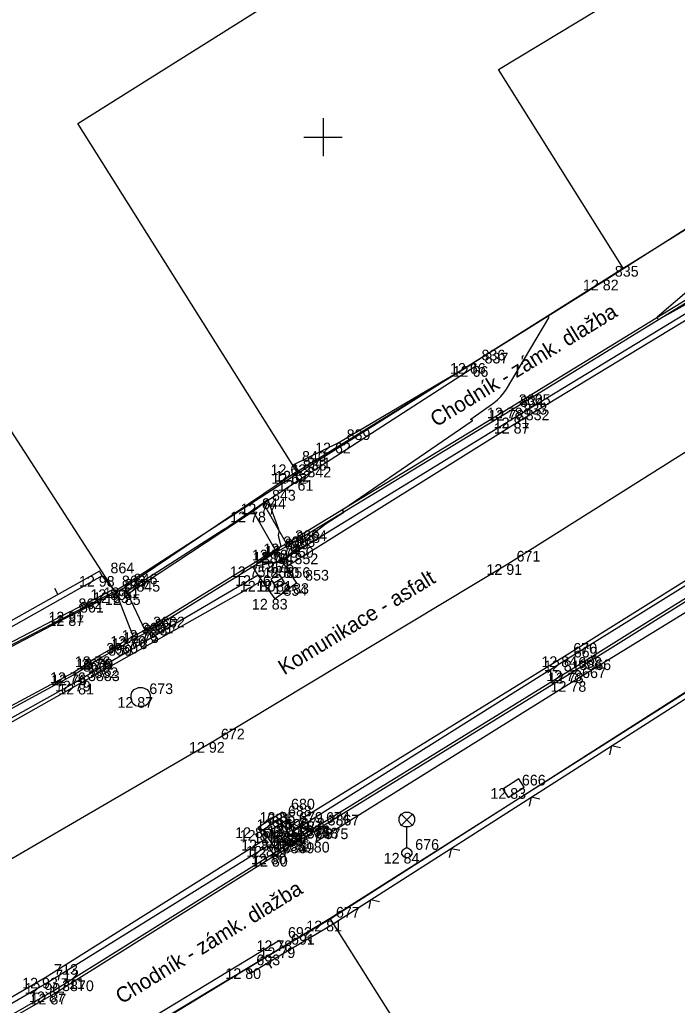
# Model space of a CAD drawing. Extents: x -703403 to -701924, y -1022520 to -1021856.
# Drawn here: x -703282.96 to -703265.7, y -1022172.79 to -1022146.91 of the extents above; entities that cross this region are included whole.
import ezdxf

# ---------------------------------------------------------------- set-up
doc = ezdxf.new("R2010")
doc.units = 0
for name, color, linetype in [('Ex_Minor Contours', 7, 'Continuous'), ('Z_body', 7, 'Continuous'), ('Z_body_cisla', 7, 'Continuous'), ('Z_body_vysky_redukovane', 7, 'Continuous'), ('Z_budova', 7, 'Continuous'), ('Z_chodnik', 7, 'Continuous'), ('Z_hektometricka_sit', 7, 'Continuous'), ('Z_katastr_hranice', 7, 'Continuous'), ('Z_katastr_vnitrni_kresba', 7, 'Continuous'), ('Z_komunikace', 7, 'Continuous'), ('Z_komunikace_osa', 7, 'Continuous'), ('Z_obruba', 7, 'Continuous'), ('Z_pilire', 7, 'Continuous'), ('Z_ploty', 7, 'Continuous'), ('Z_ploty_znacky', 7, 'Continuous'), ('Z_popisy', 7, 'Continuous'), ('Z_rozhranni', 7, 'Continuous'), ('Z_site_kanalizace_znaky', 7, 'Continuous'), ('Z_site_vo_znaky', 7, 'Continuous'), ('Z_vstupy', 7, 'Continuous'), ('Z_zlabek', 7, 'Continuous')]:
    doc.layers.add(name, color=color, linetype=linetype)

# ---------------------------------------------------------------- blocks, each defined once
blk = doc.blocks.new('POINT_DISPLAY')
blk.add_line((0, 0), (0, 0))
blk = doc.blocks.new('Z34')
for p, q in [((-0.15, 1.02), (-0.05, 1.07)), ((-0.05, 1.07), (0.05, 1.07)), ((0.05, 1.07), (0.15, 1.02)), ((-0.2, 0.93), (-0.15, 1.02)), ((-0.2, 0.82), (-0.2, 0.93)), ((-0.15, 0.72), (-0.2, 0.82)), ((0.15, 0.72), (-0.15, 1.02)), ((0.15, 1.02), (-0.15, 0.72)), ((0.15, 1.02), (0.2, 0.93)), ((0.2, 0.82), (0.15, 0.72)), ((0.2, 0.93), (0.2, 0.82)), ((-0.05, 0.68), (-0.15, 0.72)), ((0.05, 0.68), (-0.05, 0.68)), ((0, 0.13), (0, 0.68)), ((0.15, 0.72), (0.05, 0.68)), ((-0.13, 0.03), (-0.1, 0.08)), ((-0.13, -0.03), (-0.13, 0.03)), ((-0.1, 0.08), (-0.08, 0.1)), ((-0.08, 0.1), (-0.03, 0.13)), ((-0.03, 0.13), (0.03, 0.13)), ((0.03, 0.13), (0.08, 0.1)), ((0.08, 0.1), (0.1, 0.08)), ((0.1, 0.08), (0.13, 0.03)), ((0.13, 0.03), (0.13, -0.03)), ((-0.1, -0.08), (-0.13, -0.03)), ((-0.08, -0.1), (-0.1, -0.08)), ((-0.03, -0.13), (-0.08, -0.1)), ((0.03, -0.13), (-0.03, -0.13)), ((0.08, -0.1), (0.03, -0.13)), ((0.1, -0.08), (0.08, -0.1)), ((0.13, -0.03), (0.1, -0.08))]:
    blk.add_line(p, q)
blk = doc.blocks.new('Z666')
for p, q in [((-0.25, 0.13), (-0.25, -0.13)), ((0.25, 0.13), (-0.25, 0.13)), ((0.25, -0.13), (0.25, 0.13)), ((-0.25, -0.13), (0.25, -0.13))]:
    blk.add_line(p, q)
blk = doc.blocks.new('Z620')
for p, q in [((-0.25, 0.05), (-0.23, 0.13)), ((-0.25, -0.05), (-0.25, 0.05)), ((-0.23, 0.13), (-0.17, 0.2)), ((-0.17, 0.2), (-0.05, 0.25)), ((-0.05, 0.25), (0.05, 0.25)), ((0.05, 0.25), (0.17, 0.2)), ((0.17, 0.2), (0.23, 0.13)), ((0.23, 0.13), (0.25, 0.05)), ((0.25, 0.05), (0.25, -0.05)), ((-0.2, -0.17), (-0.25, -0.05)), ((-0.13, -0.23), (-0.2, -0.17)), ((-0.05, -0.25), (-0.13, -0.23)), ((0.05, -0.25), (-0.05, -0.25)), ((0.13, -0.23), (0.05, -0.25)), ((0.2, -0.17), (0.13, -0.23)), ((0.25, -0.05), (0.2, -0.17))]:
    blk.add_line(p, q)
blk = doc.blocks.new('Z46260')
for p, q in [((0.13, 0.13), (-0.13, 0.13)), ((-0.13, 0.13), (-0.13, -0.13)), ((0.13, 0), (-0.13, 0)), ((0.13, -0.13), (0.13, 0.13)), ((-0.13, -0.13), (0.13, -0.13))]:
    blk.add_line(p, q)
blk = doc.blocks.new('Z210')
blk.add_line((0, 0), (0, 0.17))
blk = doc.blocks.new('Z212')
for p, q in [((-0.17, 0.17), (0, 0)), ((0, 0), (0.17, 0.17))]:
    blk.add_line(p, q)

msp = doc.modelspace()

# ---------------------------------------------------------------- linework, layer by layer
at = {"layer": 'Ex_Minor Contours'}
for points in [[(-703264.422, -1022153.187), (-703266.229, -1022154.725), (-703266.231, -1022154.727), (-703266.232, -1022154.731), (-703266.232, -1022154.734), (-703266.231, -1022154.738), (-703266.224, -1022154.753), (-703266.22, -1022154.76), (-703266.215, -1022154.767), (-703266.205, -1022154.783), (-703266.202, -1022154.786), (-703266.199, -1022154.787), (-703266.196, -1022154.787), (-703266.192, -1022154.786), (-703262.3, -1022152.622)], [(-703280.346, -1022161.903), (-703280.202, -1022161.919), (-703280.178, -1022161.92), (-703280.155, -1022161.917), (-703280.133, -1022161.91), (-703280.112, -1022161.899), (-703277.628, -1022160.311), (-703277.526, -1022160.246), (-703277.426, -1022160.18), (-703277.325, -1022160.113), (-703277.225, -1022160.046), (-703276.672, -1022159.671), (-703276.65, -1022159.656), (-703276.628, -1022159.64), (-703276.606, -1022159.625), (-703276.584, -1022159.609), (-703276.458, -1022159.518), (-703276.455, -1022159.516), (-703276.453, -1022159.516), (-703276.451, -1022159.518), (-703276.45, -1022159.521), (-703276.445, -1022159.539), (-703276.441, -1022159.55), (-703276.172, -1022160.287), (-703276.167, -1022160.304), (-703276.164, -1022160.32), (-703276.163, -1022160.338), (-703276.164, -1022160.355), (-703276.173, -1022160.425), (-703276.175, -1022160.442), (-703276.174, -1022160.46), (-703276.173, -1022160.477), (-703276.17, -1022160.494), (-703276.12, -1022160.708), (-703276.118, -1022160.728), (-703276.121, -1022160.746), (-703276.13, -1022160.763), (-703276.144, -1022160.778), (-703276.211, -1022160.833), (-703276.228, -1022160.846), (-703276.246, -1022160.859), (-703276.263, -1022160.872), (-703276.281, -1022160.885), (-703276.691, -1022161.168), (-703276.745, -1022161.21), (-703276.759, -1022161.236), (-703276.731, -1022161.244), (-703276.663, -1022161.235), (-703276.278, -1022161.158), (-703276.186, -1022161.133), (-703276.101, -1022161.098), (-703276.02, -1022161.053), (-703275.945, -1022160.996), (-703275.209, -1022160.369), (-703275.138, -1022160.31), (-703275.065, -1022160.253), (-703274.991, -1022160.198), (-703274.915, -1022160.146), (-703274.456, -1022159.84), (-703274.455, -1022159.839), (-703274.454, -1022159.837), (-703274.454, -1022159.836), (-703274.455, -1022159.834), (-703274.485, -1022159.789), (-703274.488, -1022159.783), (-703274.488, -1022159.778), (-703274.486, -1022159.774), (-703274.481, -1022159.77), (-703271.082, -1022157.445), (-703271.077, -1022157.44), (-703271.075, -1022157.436), (-703271.078, -1022157.433), (-703271.084, -1022157.429), (-703271.116, -1022157.417), (-703271.123, -1022157.414), (-703271.125, -1022157.41), (-703271.124, -1022157.406), (-703271.118, -1022157.401), (-703270.519, -1022156.973), (-703270.422, -1022156.896), (-703270.334, -1022156.81), (-703270.255, -1022156.715), (-703270.186, -1022156.612), (-703269.072, -1022154.743), (-703269.07, -1022154.738), (-703269.07, -1022154.733), (-703269.071, -1022154.729), (-703269.074, -1022154.724), (-703269.097, -1022154.698)], [(-703279.64, -1022163), (-703276.84, -1022161.27)]]:
    msp.add_lwpolyline(points, dxfattribs=at)
at = {"layer": 'Z_budova'}
for p, q in [((-703259.29, -1022148.47), (-703267.57, -1022153.74)), ((-703267.57, -1022153.74), (-703271.06, -1022155.93)), ((-703275.77, -1022158.59), (-703275.65, -1022158.76)), ((-703275.75, -1022158.82), (-703280.2, -1022161.82)), ((-703275.65, -1022158.76), (-703275.75, -1022158.82)), ((-703280.8, -1022161.52), (-703280.87, -1022161.39)), ((-703280.5, -1022161.87), (-703280.8, -1022161.52)), ((-703280.43, -1022161.95), (-703280.5, -1022161.87)), ((-703280.2, -1022161.82), (-703280.43, -1022161.95))]:
    msp.add_line(p, q, dxfattribs=at)
at = {"layer": 'Z_chodnik'}
for p, q in [((-703275.63, -1022159), (-703276.56, -1022159.62)), ((-703276.56, -1022159.62), (-703276.83, -1022159.83)), ((-703276.83, -1022159.83), (-703280.12, -1022162)), ((-703281.6, -1022162.55), (-703280.43, -1022161.95)), ((-703281.6, -1022162.55), (-703288.9, -1022166.36))]:
    msp.add_line(p, q, dxfattribs=at)
at = {"layer": 'Z_hektometricka_sit'}
for p, q in [((-703275, -1022149.5), (-703275, -1022150.5)), ((-703275.5, -1022150), (-703274.5, -1022150))]:
    msp.add_line(p, q, dxfattribs=at)
at = {"layer": 'Z_katastr_hranice'}
for p, q in [((-703267.12, -1022153.44), (-703258.63, -1022148.12)), ((-703289.16, -1022148.5), (-703280.47, -1022161.93)), ((-703275.66, -1022158.82), (-703267.12, -1022153.44)), ((-703280.47, -1022161.93), (-703275.66, -1022158.82)), ((-703286.64, -1022165.11), (-703280.47, -1022161.93)), ((-703263.07, -1022163.05), (-703274.81, -1022170.51)), ((-703274.81, -1022170.51), (-703280.91, -1022174.18)), ((-703266.89, -1022183.1), (-703274.81, -1022170.51))]:
    msp.add_line(p, q, dxfattribs=at)
at = {"layer": 'Z_katastr_vnitrni_kresba'}
for p, q in [((-703270.39, -1022148.22), (-703261.74, -1022142.98)), ((-703281.44, -1022149.64), (-703275, -1022145.59)), ((-703267.12, -1022153.44), (-703270.39, -1022148.22)), ((-703275.66, -1022158.82), (-703281.44, -1022149.64))]:
    msp.add_line(p, q, dxfattribs=at)
at = {"layer": 'Z_komunikace'}
for p, q in [((-703262.14, -1022152.78), (-703269.91, -1022157.5)), ((-703269.91, -1022157.5), (-703275.98, -1022161.29)), ((-703259.69, -1022158.01), (-703268.66, -1022163.63)), ((-703275.98, -1022161.29), (-703275.7, -1022161.71)), ((-703276.6, -1022161.65), (-703281.39, -1022164.35)), ((-703276.26, -1022162.12), (-703276.6, -1022161.65)), ((-703275.7, -1022161.71), (-703276.26, -1022162.12)), ((-703268.66, -1022163.63), (-703275.85, -1022168.08)), ((-703281.39, -1022164.35), (-703287.19, -1022167.62)), ((-703276.06, -1022167.72), (-703276.7, -1022168.12)), ((-703275.85, -1022168.08), (-703276.06, -1022167.72)), ((-703276.7, -1022168.12), (-703276.54, -1022168.45)), ((-703276.54, -1022168.45), (-703282.29, -1022172.07)), ((-703282.29, -1022172.07), (-703287.29, -1022174.96))]:
    msp.add_line(p, q, dxfattribs=at)
at = {"layer": 'Z_komunikace_osa'}
for p, q in [((-703261.03, -1022155.45), (-703270.15, -1022161.21)), ((-703270.15, -1022161.21), (-703277.91, -1022165.88)), ((-703277.91, -1022165.88), (-703283.89, -1022169.36))]:
    msp.add_line(p, q, dxfattribs=at)
at = {"layer": 'Z_obruba'}
for p, q in [((-703270.09, -1022157.1), (-703262.38, -1022152.36)), ((-703262.23, -1022152.66), (-703269.96, -1022157.36)), ((-703275.96, -1022160.67), (-703270.09, -1022157.1)), ((-703269.96, -1022157.36), (-703276.09, -1022161.12)), ((-703259.63, -1022158.12), (-703268.64, -1022163.74)), ((-703276.26, -1022160.83), (-703275.96, -1022160.67)), ((-703279.68, -1022162.94), (-703276.26, -1022160.83)), ((-703276.7, -1022161.5), (-703281.43, -1022164.27)), ((-703268.49, -1022164.06), (-703264.42, -1022161.52)), ((-703281.65, -1022162.46), (-703280.5, -1022161.87)), ((-703281.65, -1022162.46), (-703288.95, -1022166.27)), ((-703280.91, -1022163.63), (-703279.98, -1022163.1)), ((-703279.98, -1022163.1), (-703279.68, -1022162.94)), ((-703281.56, -1022164.05), (-703280.91, -1022163.63)), ((-703268.64, -1022163.74), (-703275.8, -1022168.24)), ((-703287.4, -1022167.19), (-703281.56, -1022164.05)), ((-703275.1, -1022168.14), (-703268.49, -1022164.06)), ((-703281.43, -1022164.27), (-703287.21, -1022167.5)), ((-703275.65, -1022168.48), (-703275.1, -1022168.14)), ((-703276.28, -1022168.87), (-703275.65, -1022168.48)), ((-703276.46, -1022168.61), (-703282.25, -1022172.21)), ((-703282.07, -1022172.49), (-703276.28, -1022168.87)), ((-703282.25, -1022172.21), (-703287.23, -1022175.09)), ((-703287.02, -1022175.32), (-703282.07, -1022172.49))]:
    msp.add_line(p, q, dxfattribs=at)
at = {"layer": 'Z_ploty'}
for p, q in [((-703280.87, -1022161.39), (-703284.76, -1022163.58)), ((-703280.8, -1022161.52), (-703284.69, -1022163.71)), ((-703274.88, -1022170.57), (-703263.42, -1022163.24)), ((-703274.8, -1022170.7), (-703263.35, -1022163.37)), ((-703276.06, -1022171.27), (-703274.88, -1022170.57)), ((-703275.98, -1022171.39), (-703274.8, -1022170.7)), ((-703276.98, -1022171.82), (-703276.06, -1022171.27)), ((-703276.9, -1022171.95), (-703275.98, -1022171.39)), ((-703276.98, -1022171.82), (-703276.9, -1022171.95))]:
    msp.add_line(p, q, dxfattribs=at)
at = {"layer": 'Z_rozhranni'}
for p, q in [((-703276.23, -1022160.89), (-703276.09, -1022161.12)), ((-703276.7, -1022161.5), (-703276.84, -1022161.27)), ((-703276.09, -1022161.12), (-703275.98, -1022161.29)), ((-703276.6, -1022161.65), (-703276.7, -1022161.5)), ((-703276.14, -1022167.91), (-703276.58, -1022168.19)), ((-703275.86, -1022168.32), (-703276.14, -1022167.91)), ((-703276.58, -1022168.19), (-703276.29, -1022168.63)), ((-703275.85, -1022168.08), (-703275.8, -1022168.24)), ((-703275.8, -1022168.24), (-703275.68, -1022168.42)), ((-703276.54, -1022168.45), (-703276.46, -1022168.61)), ((-703276.29, -1022168.63), (-703275.86, -1022168.32)), ((-703276.46, -1022168.61), (-703276.31, -1022168.81))]:
    msp.add_line(p, q, dxfattribs=at)
at = {"layer": 'Z_vstupy'}
for p, q in [((-703274.6, -1022158.02), (-703271.06, -1022155.93)), ((-703275.77, -1022158.59), (-703274.6, -1022158.02)), ((-703280.02, -1022173.66), (-703276.98, -1022171.82))]:
    msp.add_line(p, q, dxfattribs=at)
at = {"layer": 'Z_zlabek'}
for p, q in [((-703270.05, -1022157.16), (-703262.35, -1022152.42)), ((-703275.65, -1022158.76), (-703271.06, -1022155.93)), ((-703270.99, -1022156.01), (-703275.63, -1022159)), ((-703271.06, -1022155.93), (-703270.99, -1022156.01)), ((-703275.92, -1022160.73), (-703270.05, -1022157.16)), ((-703275.63, -1022159), (-703275.75, -1022158.82)), ((-703275.96, -1022160.67), (-703276.56, -1022159.62)), ((-703276.83, -1022159.83), (-703276.26, -1022160.83)), ((-703276.23, -1022160.89), (-703275.92, -1022160.73)), ((-703276.84, -1022161.27), (-703276.23, -1022160.89)), ((-703279.64, -1022163), (-703276.84, -1022161.27)), ((-703268.53, -1022164), (-703264.46, -1022161.46)), ((-703264.4, -1022161.81), (-703268.42, -1022164.28)), ((-703279.98, -1022163.1), (-703280.43, -1022161.95)), ((-703280.2, -1022161.82), (-703280.12, -1022162)), ((-703280.12, -1022162), (-703279.68, -1022162.94)), ((-703279.94, -1022163.16), (-703279.64, -1022163)), ((-703280.87, -1022163.69), (-703279.94, -1022163.16)), ((-703281.53, -1022164.11), (-703280.87, -1022163.69)), ((-703287.37, -1022167.26), (-703281.53, -1022164.11)), ((-703275.14, -1022168.08), (-703268.53, -1022164)), ((-703268.42, -1022164.28), (-703275.18, -1022168.5)), ((-703275.68, -1022168.42), (-703275.14, -1022168.08)), ((-703275.18, -1022168.5), (-703275.1, -1022168.14)), ((-703276.31, -1022168.81), (-703275.68, -1022168.42)), ((-703282.11, -1022172.43), (-703276.31, -1022168.81)), ((-703276.14, -1022171.09), (-703280.22, -1022173.56)), ((-703276.14, -1022171.09), (-703276.06, -1022171.27)), ((-703287.06, -1022175.26), (-703282.11, -1022172.43))]:
    msp.add_line(p, q, dxfattribs=at)

# ---------------------------------------------------------------- block references
at = {"layer": 'Z_body'}
for p in [(-703267.57, -1022153.74), (-703271.06, -1022155.93), (-703270.99, -1022156.01), (-703270.09, -1022157.1), (-703270.05, -1022157.16), (-703269.96, -1022157.36), (-703269.91, -1022157.5), (-703274.6, -1022158.02), (-703275.77, -1022158.59), (-703275.75, -1022158.82), (-703275.65, -1022158.76), (-703275.63, -1022159), (-703276.56, -1022159.62), (-703276.83, -1022159.83), (-703275.96, -1022160.67), (-703275.92, -1022160.73), (-703276.26, -1022160.83), (-703276.23, -1022160.89), (-703276.84, -1022161.27), (-703276.09, -1022161.12), (-703275.98, -1022161.29), (-703270.15, -1022161.21), (-703280.8, -1022161.52), (-703276.7, -1022161.5), (-703276.6, -1022161.65), (-703276.19, -1022161.65), (-703275.7, -1022161.71), (-703280.5, -1022161.87), (-703280.43, -1022161.95), (-703280.2, -1022161.82), (-703280.12, -1022162), (-703276.26, -1022162.12), (-703281.65, -1022162.46), (-703281.6, -1022162.55), (-703279.98, -1022163.1), (-703279.68, -1022162.94), (-703279.64, -1022163), (-703279.94, -1022163.16), (-703280.91, -1022163.63), (-703280.87, -1022163.69), (-703268.66, -1022163.63), (-703268.64, -1022163.74), (-703281.56, -1022164.05), (-703281.53, -1022164.11), (-703268.53, -1022164), (-703268.49, -1022164.06), (-703281.43, -1022164.27), (-703281.39, -1022164.35), (-703268.42, -1022164.28), (-703279.79, -1022164.7), (-703277.91, -1022165.88), (-703270, -1022167.09), (-703276.06, -1022167.72), (-703276.14, -1022167.91), (-703276.7, -1022168.12), (-703276.58, -1022168.19), (-703276.22, -1022168.25), (-703275.85, -1022168.08), (-703275.8, -1022168.24), (-703275.14, -1022168.08), (-703275.1, -1022168.14), (-703276.54, -1022168.45), (-703275.86, -1022168.32), (-703275.68, -1022168.42), (-703275.65, -1022168.48), (-703275.18, -1022168.5), (-703276.46, -1022168.61), (-703276.29, -1022168.63), (-703272.8, -1022168.79), (-703276.31, -1022168.81), (-703276.28, -1022168.87), (-703274.88, -1022170.57), (-703276.14, -1022171.09), (-703276.06, -1022171.27), (-703276.98, -1022171.82), (-703282.29, -1022172.07), (-703282.25, -1022172.21), (-703282.11, -1022172.43), (-703282.07, -1022172.49)]:
    msp.add_blockref('POINT_DISPLAY', p, dxfattribs=at)
at = {"layer": 'Z_pilire', "rotation": 32.4}
msp.add_blockref('Z666', (-703270, -1022167.09), dxfattribs=at)
at = {"layer": 'Z_ploty_znacky'}
for name, p, rotation in [('Z210', (-703281.96, -1022162), 29.4), ('Z212', (-703267.43, -1022165.98), -147.4), ('Z212', (-703269.54, -1022167.33), -147.4), ('Z212', (-703271.64, -1022168.68), -147.4), ('Z212', (-703273.75, -1022170.02), -147.4), ('Z210', (-703275.39, -1022171.05), -149.40000000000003), ('Z210', (-703276.44, -1022171.67), -148.90000000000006)]:
    msp.add_blockref(name, p, dxfattribs=dict(at, rotation=rotation))
at = {"layer": 'Z_site_kanalizace_znaky', "rotation": 31.5}
for p in [(-703276.19, -1022161.65), (-703276.22, -1022168.25)]:
    msp.add_blockref('Z46260', p, dxfattribs=at)
at = {"layer": 'Z_site_kanalizace_znaky'}
msp.add_blockref('Z620', (-703279.79, -1022164.7), dxfattribs=at)
at = {"layer": 'Z_site_vo_znaky'}
msp.add_blockref('Z34', (-703272.8, -1022168.79), dxfattribs=at)

# ---------------------------------------------------------------- texts
at = {"layer": 'Z_body_cisla'}
for s, p in [('835', (-703267.34, -1022153.66)), ('836', (-703270.84, -1022155.86)), ('837', (-703270.76, -1022155.94)), ('3665', (-703269.86, -1022157.03)), ('834', (-703269.83, -1022157.08)), ('833', (-703269.74, -1022157.28)), ('832', (-703269.68, -1022157.43)), ('839', (-703274.38, -1022157.95)), ('840', (-703275.55, -1022158.52)), ('841', (-703275.42, -1022158.69)), ('838', (-703275.53, -1022158.75)), ('842', (-703275.41, -1022158.93)), ('844', (-703276.6, -1022159.76)), ('843', (-703276.34, -1022159.54)), ('3663', (-703276.04, -1022160.76)), ('3664', (-703275.73, -1022160.6)), ('848', (-703275.7, -1022160.65)), ('849', (-703276, -1022160.82)), ('850', (-703275.87, -1022161.04)), ('3884', (-703276.61, -1022161.2)), ('852', (-703275.75, -1022161.21)), ('671', (-703269.92, -1022161.14)), ('864', (-703280.58, -1022161.45)), ('851', (-703276.47, -1022161.43)), ('855', (-703276.38, -1022161.57)), ('856', (-703275.96, -1022161.57)), ('863', (-703280.28, -1022161.79)), ('846', (-703279.97, -1022161.74)), ('853', (-703275.47, -1022161.64)), ('847', (-703280.21, -1022161.88)), ('845', (-703279.9, -1022161.93)), ('854', (-703276.04, -1022162.04)), ('862', (-703281.42, -1022162.39)), ('861', (-703281.38, -1022162.48)), ('3662', (-703279.46, -1022162.87)), ('3661', (-703279.76, -1022163.03)), ('858', (-703279.71, -1022163.08)), ('857', (-703279.42, -1022162.93)), ('3660', (-703280.69, -1022163.56)), ('859', (-703280.64, -1022163.61)), ('670', (-703268.43, -1022163.56)), ('669', (-703268.42, -1022163.66)), ('3659', (-703281.34, -1022163.98)), ('860', (-703281.3, -1022164.03)), ('668', (-703268.3, -1022163.93)), ('3866', (-703268.27, -1022163.99)), ('3882', (-703281.21, -1022164.2)), ('3883', (-703281.17, -1022164.28)), ('667', (-703268.2, -1022164.2)), ('673', (-703279.56, -1022164.62)), ('672', (-703277.68, -1022165.81)), ('666', (-703269.78, -1022167.02)), ('680', (-703275.84, -1022167.65)), ('681', (-703276.47, -1022168.04)), ('688', (-703275.92, -1022167.83)), ('679', (-703275.63, -1022168)), ('674', (-703274.92, -1022168)), ('689', (-703276.35, -1022168.11)), ('690', (-703276, -1022168.18)), ('687', (-703275.63, -1022168.24)), ('678', (-703275.58, -1022168.16)), ('3867', (-703274.88, -1022168.07)), ('682', (-703276.31, -1022168.37)), ('683', (-703276.24, -1022168.53)), ('686', (-703276.06, -1022168.56)), ('684', (-703275.46, -1022168.35)), ('3868', (-703275.43, -1022168.41)), ('675', (-703274.96, -1022168.43)), ('685', (-703276.09, -1022168.74)), ('3869', (-703276.06, -1022168.8)), ('676', (-703272.58, -1022168.71)), ('677', (-703274.66, -1022170.49)), ('692', (-703275.92, -1022171.02)), ('691', (-703275.84, -1022171.2)), ('693', (-703276.75, -1022171.74)), ('713', (-703282.06, -1022171.99)), ('712', (-703282.03, -1022172.14)), ('711', (-703281.88, -1022172.36)), ('3870', (-703281.85, -1022172.42))]:
    msp.add_text(s, height=0.28, dxfattribs=at).set_placement(p)
at = {"layer": 'Z_body_vysky_redukovane'}
for s, p in [('12 82', (-703268.177, -1022154.02)), ('12 66', (-703271.667, -1022156.21)), ('12 66', (-703271.597, -1022156.29)), ('12 78', (-703270.697, -1022157.38)), ('12 78', (-703270.657, -1022157.44)), ('12 81', (-703270.52, -1022157.64)), ('12 87', (-703270.517, -1022157.78)), ('12 62', (-703275.207, -1022158.3)), ('12 62', (-703276.377, -1022158.87)), ('12 62', (-703276.357, -1022159.1)), ('12 62', (-703276.257, -1022159.04)), ('12 61', (-703276.19, -1022159.28)), ('12 77', (-703277.167, -1022159.9)), ('12 78', (-703277.437, -1022160.11)), ('12 74', (-703276.567, -1022160.95)), ('12 74', (-703276.527, -1022161.01)), ('12 76', (-703276.867, -1022161.11)), ('12 74', (-703276.837, -1022161.17)), ('12 75', (-703277.447, -1022161.55)), ('12 75', (-703276.697, -1022161.4)), ('12 80', (-703276.563, -1022161.57)), ('12 91', (-703270.71, -1022161.49)), ('12 98', (-703281.407, -1022161.8)), ('12 76', (-703277.307, -1022161.78)), ('12 80', (-703277.183, -1022161.93)), ('12 81', (-703276.75, -1022161.93)), ('12 83', (-703276.307, -1022161.99)), ('12 89', (-703281.107, -1022162.15)), ('12 83', (-703281.037, -1022162.23)), ('12 61', (-703280.76, -1022162.1)), ('12 85', (-703280.727, -1022162.28)), ('12 83', (-703276.867, -1022162.4)), ('12 91', (-703282.21, -1022162.74)), ('12 87', (-703282.207, -1022162.83)), ('12 76', (-703280.587, -1022163.38)), ('12 76', (-703280.287, -1022163.22)), ('12 75', (-703280.247, -1022163.28)), ('12 76', (-703280.547, -1022163.44)), ('12 76', (-703281.517, -1022163.91)), ('12 84', (-703269.267, -1022163.91)), ('12 76', (-703281.477, -1022163.97)), ('12 81', (-703269.2, -1022164.02)), ('12 76', (-703282.167, -1022164.33)), ('12 76', (-703282.137, -1022164.39)), ('12 78', (-703269.137, -1022164.28)), ('12 78', (-703269.097, -1022164.34)), ('12 79', (-703282.037, -1022164.55)), ('12 81', (-703281.95, -1022164.63)), ('12 78', (-703269.027, -1022164.56)), ('12 87', (-703280.397, -1022164.98)), ('12 92', (-703278.517, -1022166.16)), ('12 83', (-703270.607, -1022167.37)), ('12 85', (-703276.667, -1022168)), ('12 84', (-703276.747, -1022168.19)), ('12 86', (-703277.307, -1022168.4)), ('12 84', (-703277.187, -1022168.47)), ('12 82', (-703276.827, -1022168.53)), ('12 83', (-703276.457, -1022168.36)), ('12 80', (-703276.383, -1022168.52)), ('12 78', (-703275.747, -1022168.36)), ('12 80', (-703275.683, -1022168.42)), ('12 84', (-703277.147, -1022168.73)), ('12 79', (-703276.467, -1022168.6)), ('12 79', (-703276.287, -1022168.7)), ('12 80', (-703276.233, -1022168.76)), ('12 80', (-703275.763, -1022168.78)), ('12 81', (-703277.02, -1022168.89)), ('12 79', (-703276.897, -1022168.91)), ('12 84', (-703273.407, -1022169.07)), ('12 80', (-703276.893, -1022169.09)), ('12 80', (-703276.863, -1022169.15)), ('12 81', (-703275.44, -1022170.85)), ('12 78', (-703276.747, -1022171.37)), ('12 79', (-703276.667, -1022171.55)), ('12 80', (-703277.563, -1022172.1)), ('12 93', (-703282.897, -1022172.35)), ('12 90', (-703282.833, -1022172.49)), ('12 87', (-703282.717, -1022172.71)), ('12 87', (-703282.677, -1022172.77))]:
    msp.add_text(s, height=0.28, dxfattribs=at).set_placement(p)
at = {"layer": 'Z_popisy'}
for s, p in [('Chodník - zámk. dlažba', (-703272.03, -1022157.62)), ('Komunikace - asfalt', (-703276.02, -1022164.13)), ('Chodník - zámk. dlažba', (-703280.29, -1022172.77))]:
    msp.add_text(s, height=0.4, rotation=31.5, dxfattribs=at).set_placement(p)

doc.saveas('drawing.dxf')
